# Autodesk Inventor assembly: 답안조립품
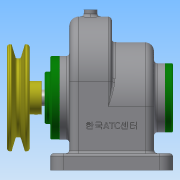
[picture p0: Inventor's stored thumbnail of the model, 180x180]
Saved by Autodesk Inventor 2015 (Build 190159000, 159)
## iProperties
Created: 2017-11
Part Number: 답안조립품
Document SubType Name: Assembly
Designer: user
Author: user
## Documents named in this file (14)
- C:\Users\user\Desktop\471107v1004\답안조립품.iam
- C:\Users\user\Desktop\471107v1004\1본체.ipt
- C:\Users\user\Desktop\471107v1004\축.ipt
- C:\Users\user\Desktop\471107v1004\베어링 6002.ipt
- C:\Users\user\Desktop\471107v1004\키 - 6 x 6 x 22.ipt
- C:\Users\user\Desktop\471107v1004\스퍼기어.ipt
- C:\Users\user\Desktop\471107v1004\V-벨트풀리.ipt
- C:\Users\user\Desktop\471107v1004\키 - 5 x 5 x 18.ipt
- C:\Users\user\Desktop\471107v1004\앞커버.ipt
- C:\Users\user\Desktop\471107v1004\오일 실 15 30 7.ipt
- C:\Users\user\Desktop\471107v1004\멈춤나사 - M4 x 10.ipt
- 멈춤나사 - M4 x 10.ipt
- C:\Users\user\Desktop\471107v1004\볼트 M3 x 8.ipt
- C:\Users\user\Desktop\471107v1004\뒤커버.ipt
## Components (2 placed, 2 different names)
1. 1본체:1
2. V-벨트풀리:2
